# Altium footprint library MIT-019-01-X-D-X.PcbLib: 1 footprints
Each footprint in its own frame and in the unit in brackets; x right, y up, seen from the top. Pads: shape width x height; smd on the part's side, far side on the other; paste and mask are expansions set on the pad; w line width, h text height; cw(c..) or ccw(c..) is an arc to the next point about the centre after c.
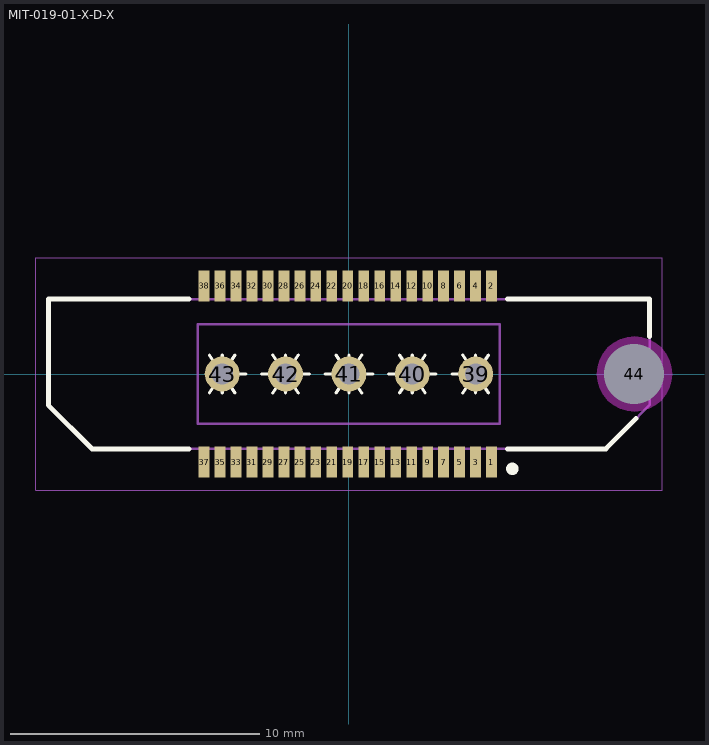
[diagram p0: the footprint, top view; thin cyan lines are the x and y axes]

## MIT-019-01-X-D-X [mm] "0.635mm pitch, 38 pin, mixed technology high speed terminal"
height 4.27
pads (44):
  rect 0.43x1.25 smd mask+0: 1(5.715,-3.53) 2(5.715,3.53) 3(5.075,-3.53) 4(5.075,3.53) 5(4.435,-3.53) 6(4.435,3.53) 7(3.795,-3.53) 8(3.795,3.53) 9(3.155,-3.53) 10(3.155,3.53) 11(2.515,-3.53) 12(2.515,3.53) 13(1.875,-3.53) 14(1.875,3.53) 15(1.235,-3.53) 16(1.235,3.53) 17(0.595,-3.53) 18(0.595,3.53) 19(-0.045,-3.53) 20(-0.045,3.53) 21(-0.685,-3.53) 22(-0.685,3.53) 23(-1.325,-3.53) 24(-1.325,3.53) 25(-1.965,-3.53) 26(-1.965,3.53) 27(-2.605,-3.53) 28(-2.605,3.53) 29(-3.245,-3.53) 30(-3.245,3.53) 31(-3.885,-3.53) 32(-3.885,3.53) 33(-4.525,-3.53) 34(-4.525,3.53) 35(-5.165,-3.53) 36(-5.165,3.53) 37(-5.805,-3.53) 38(-5.805,3.53)
  round 1.4 hole 0.85 mask+0: 39(5.08,0) 40(2.54,0) 41(0,0) 42(-2.54,0) 43(-5.08,0)
  round 1 hole 2.4 unplated mask+0: 44(11.43,0)
Top Overlay:
  circle w0.25: c6.55,-3.8 r0.125
  lines w0.127: -5.594,-0.762 -4.566,0.762 ; -5.594,0.762 -4.566,-0.762 ; -5.08,-0.762 -5.08,0.762 ; -5.08,0 -4.128,0 ; -3.492,0 -1.588,0 ; -3.054,-0.762 -2.026,0.762 ; -3.054,0.762 -2.026,-0.762 ; -2.54,-0.762 -2.54,0.762 ; -0.952,0 0.952,0 ; -0.514,-0.762 0.514,0.762 ; -0.514,0.762 0.514,-0.762 ; 0,-0.762 0,0.762 ; 1.588,0 3.492,0 ; 2.026,-0.762 3.054,0.762 ; 2.026,0.762 3.054,-0.762 ; 2.54,-0.762 2.54,0.762 ; 4.128,0 5.08,0 ; 4.566,-0.762 5.594,0.762 ; 4.566,0.762 5.594,-0.762 ; 5.08,-0.762 5.08,0.762
  lines w0.2: -6.4,-3 -10.3,-3 -12.05,-1.25 -12.05,3 -6.4,3 ; 6.35,-3 10.3,-3 11.5,-1.787 ; 6.35,3 12.05,3 12.05,1.5
Keep-Out Layer:
  pour cut-out: 12.957,0 12.928,0.294 12.843,0.577 12.703,0.837 12.516,1.066 12.287,1.253 12.027,1.393 11.744,1.478 11.45,1.507 11.156,1.478 10.873,1.393 10.613,1.253 10.384,1.066 10.197,0.837 10.057,0.577 9.972,0.294 9.943,0 9.972,-0.294 10.057,-0.577 10.197,-0.837 10.384,-1.066 10.613,-1.253 10.873,-1.393 11.156,-1.478 11.45,-1.507 11.744,-1.478 12.027,-1.393 12.287,-1.253 12.516,-1.066 12.703,-0.837 12.843,-0.577 12.928,-0.294
Mechanical 12:
  lines w0.001: -12.05,-1.239 -10.318,-3 10.318,-3 12.05,-1.239 12.05,3 -12.05,3 -12.05,-1.239
Mechanical 13:
  lines w0.1: -12.05,-1.239 -10.318,-3 10.318,-3 12.05,-1.239 12.05,3 -12.05,3 -12.05,-1.239 ; -6.05,-2 6.05,-2 6.05,2 -6.05,2 -6.05,-2
  text ".Designator" at 0.254,0.254 h1.52
Mechanical 15:
  lines w0.05: -0.5,0 0.5,0 ; 0,-0.5 0,0.5 ; -12.55,-4.65 12.55,-4.65 12.55,4.65 -12.55,4.65 -12.55,-4.65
